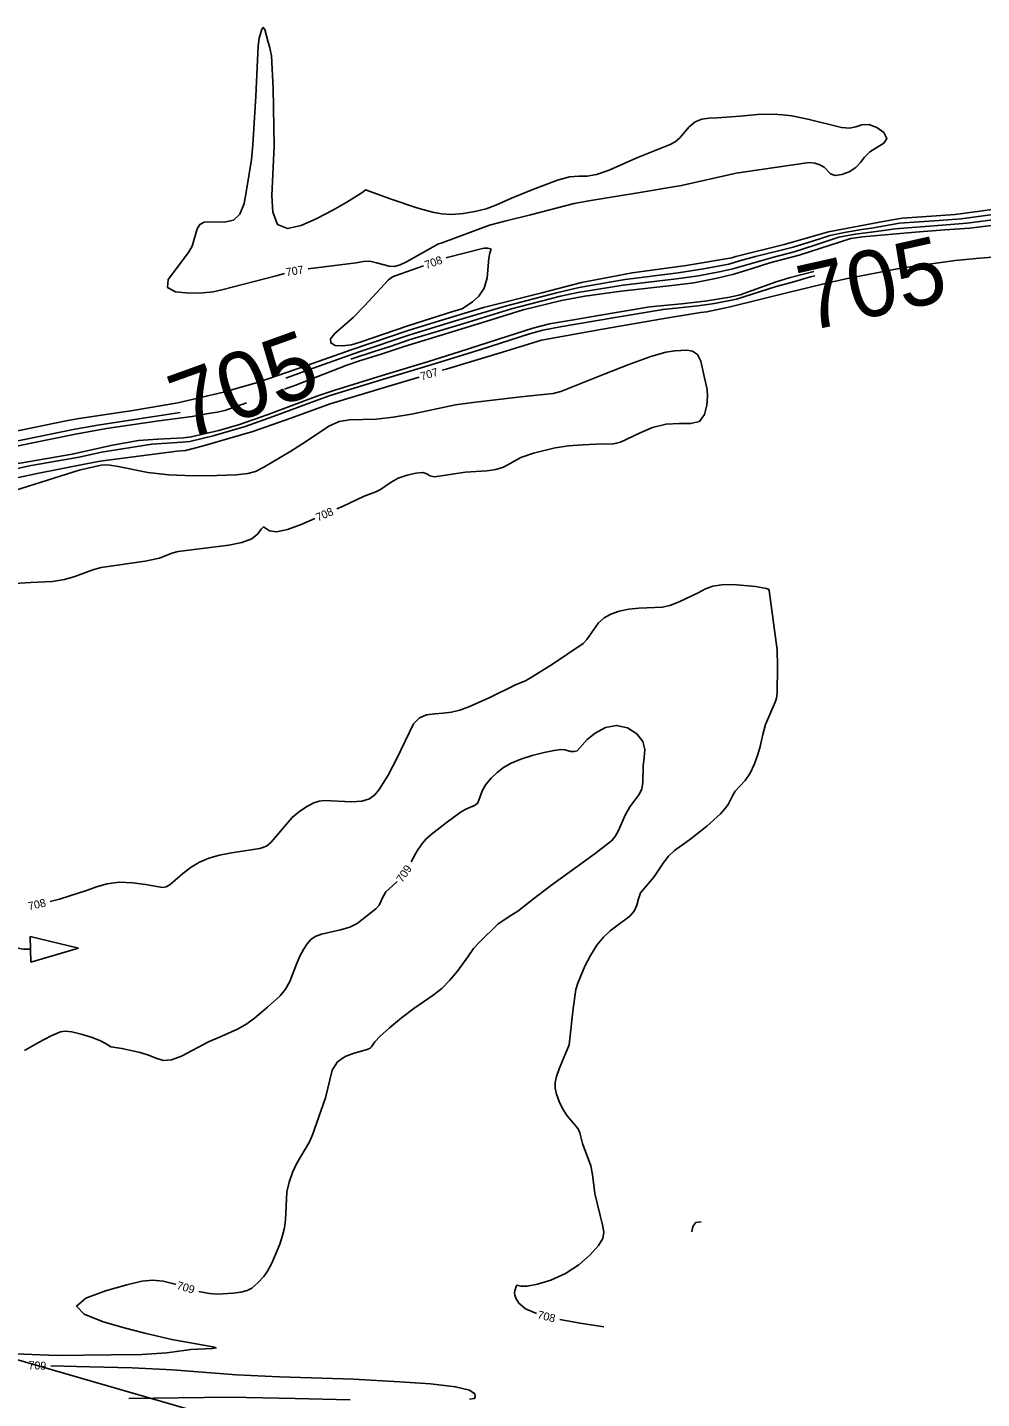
# Model space of a CAD drawing. Extents: x -468548933 to 3387700, y -306089263 to 1207014.
# Drawn here: x 1840930 to 1841407, y 538847 to 539532 of the extents above; entities that cross this region are included whole.
import ezdxf

# ---------------------------------------------------------------- set-up
doc = ezdxf.new("R2010")
doc.units = 0
for name, color, linetype in [('DT_X_Contour_Minor', 7, 'Continuous'), ('Level 19', 7, 'Continuous'), ('Level 56', 7, 'Continuous'), ('SC_Scratch1', 7, 'Continuous')]:
    doc.layers.add(name, color=color, linetype=linetype)

msp = doc.modelspace()

# ---------------------------------------------------------------- linework, layer by layer
at = {"layer": 'DT_X_Contour_Minor'}
for points in [[(1841070.63, 539411.28), (1841094.59, 539414.28), (1841098.25, 539414.92), (1841101.45, 539414.99), (1841104.77, 539414.29), (1841111.21, 539412.47), (1841113.9, 539412.4), (1841116.59, 539413.16), (1841119.79, 539414.74), (1841135.82, 539423.66), (1841137.2, 539424.03), (1841161.32, 539432.95), (1841168.97, 539435.07), (1841181.73, 539438.24), (1841203.72, 539443.89), (1841212.05, 539445.37), (1841233.42, 539448.92), (1841257.34, 539452.83), (1841284.64, 539458.97), (1841295.98, 539460.75), (1841321.05, 539464.34), (1841323.89, 539464.03), (1841326.45, 539463.23), (1841328.57, 539461.94), (1841331.85, 539458.75), (1841334.13, 539457.93), (1841337.4, 539458.28), (1841341.1, 539459.65), (1841344.4, 539461.78), (1841346.78, 539464.36), (1841348.83, 539467.1), (1841351.45, 539469.68), (1841358.49, 539474.03), (1841360.01, 539476.43), (1841358.51, 539479.28), (1841354.96, 539481.9), (1841350.92, 539483.4), (1841347.52, 539483.26), (1841344.51, 539482.26), (1841341.23, 539481.53), (1841337.26, 539481.89), (1841320.54, 539486.09), (1841312.39, 539487.62), (1841307.76, 539488.23), (1841303.22, 539488.51), (1841295.34, 539488.35), (1841286.64, 539487.58), (1841275.18, 539486.64), (1841271.21, 539486.46), (1841267.49, 539485.96), (1841264.12, 539484.63), (1841261.19, 539482.21), (1841256.3, 539476.55), (1841254.08, 539474.68), (1841251.69, 539473.41), (1841234.98, 539466.7), (1841221.14, 539460.48), (1841214.89, 539458.3), (1841210.12, 539457.59), (1841206.01, 539457.56), (1841201.36, 539457.13), (1841195.38, 539455.51), (1841183.01, 539450.85), (1841172.29, 539446.5), (1841164.52, 539443.02), (1841159.62, 539441.26), (1841154.06, 539439.8), (1841148.2, 539438.81), (1841142.51, 539438.44), (1841137.36, 539438.75), (1841132.77, 539439.56), (1841125.06, 539441.68), (1841112.58, 539445.92), (1841099.35, 539450.63), (1841098.06, 539449.58), (1841089.99, 539444.5), (1841082.96, 539440.46), (1841075.05, 539436.29), (1841067.19, 539432.83), (1841060.32, 539431.37), (1841055.4, 539433.35), (1841053.05, 539439.52), (1841052.57, 539447.87), (1841053.69, 539472.46), (1841053.12, 539501.29), (1841052.28, 539517.74), (1841051.32, 539522.29), (1841050.65, 539524.47), (1841049, 539530.83), (1841048.23, 539531.86), (1841047.46, 539530.94), (1841046.21, 539526.41), (1841045.7, 539522.58), (1841044.44, 539497.49), (1841043.02, 539473.13), (1841042.29, 539465.8), (1841039.91, 539450.48), (1841038.61, 539443.89), (1841036.49, 539438.5), (1841033.34, 539435.59), (1841029.51, 539434.64)], [(1840922.25, 539329.55), (1840949.7, 539335.19), (1840956.21, 539336.43), (1840982.93, 539340.45), (1841005.45, 539344.29), (1841028.32, 539349.57), (1841045.28, 539354.45), (1841070.02, 539362.87), (1841092.19, 539370.66), (1841120.71, 539380.38), (1841134.15, 539384.58), (1841158.38, 539391.84), (1841187.45, 539399.27), (1841207.27, 539404.37), (1841222.08, 539407.29), (1841232.58, 539409.22), (1841259.65, 539412.88), (1841282.39, 539416.79), (1841284.5, 539417.39), (1841308.65, 539423.35), (1841330.83, 539429.71), (1841358.98, 539435.09), (1841367.65, 539436.57), (1841377.39, 539437.22), (1841394.09, 539438.31), (1841418.72, 539441.67)], [(1841059.52, 539356.57), (1841070.84, 539360.65), (1841096.15, 539369.74), (1841120.94, 539378.02), (1841143.08, 539384.81), (1841168.58, 539392.39), (1841195.49, 539399.31), (1841206.06, 539401.8), (1841221.25, 539404.58), (1841229.13, 539405.91), (1841255.6, 539409.26), (1841268.3, 539411.22), (1841280.91, 539413.54), (1841286.37, 539415.17), (1841294.31, 539417.31), (1841313.14, 539422.12), (1841326.48, 539426.26), (1841331.48, 539427.89), (1841339.65, 539429.6), (1841348.48, 539431.05), (1841352.33, 539431.59), (1841366.24, 539433.95), (1841385.91, 539435.31), (1841397.12, 539436.18), (1841419.05, 539439.13)], [(1841029.51, 539434.64), (1841018.73, 539434.46), (1841016.47, 539433.37), (1841015.16, 539431.26), (1841012.69, 539422.55), (1841010.86, 539419.45), (1841000.66, 539405.86), (1841000.36, 539401.89), (1841004.41, 539399.71), (1841011.11, 539399.01), (1841017.95, 539399.2), (1841023.12, 539399.79), (1841027.5, 539400.75), (1841054.63, 539407.79), (1841058.87, 539408.88)], [(1841058.9, 539351.07), (1841064, 539352.91), (1841090.01, 539363.03), (1841096.34, 539365.27), (1841107.19, 539368.57), (1841114.11, 539370.85), (1841118.64, 539372.46), (1841142.61, 539379.65), (1841162.58, 539385.88), (1841178.23, 539390.77), (1841197.33, 539395.39), (1841208.95, 539397.55), (1841227.12, 539400.02), (1841253.93, 539403.03), (1841263.4, 539404.27), (1841275.11, 539406.52), (1841283.45, 539408.47), (1841292.56, 539411.37), (1841301.5, 539414.17), (1841316.16, 539417.98), (1841342.04, 539426.35), (1841347.87, 539427.18), (1841374.14, 539429.59), (1841389.03, 539430.67), (1841401.38, 539431.56), (1841423.01, 539434.15)], [(1841091.98, 539366.04), (1841092.47, 539366.22), (1841104.1, 539369.99), (1841111.73, 539372.42), (1841121.17, 539375.67), (1841146.31, 539383.29), (1841172.27, 539391.26), (1841196.76, 539397.5), (1841205.55, 539399.35), (1841228.12, 539402.97), (1841254.77, 539406.14), (1841265.85, 539407.74), (1841277.01, 539409.81), (1841282.97, 539411.2), (1841302.73, 539416.91), (1841313.69, 539419.76), (1841323.41, 539422.82), (1841336.04, 539426.97), (1841344.18, 539428.59), (1841349.43, 539429.23), (1841355.91, 539430.06), (1841364.1, 539431.26), (1841389.83, 539433.14), (1841399.96, 539433.98), (1841418.18, 539436.35)], [(1841139.64, 539416.71), (1841140.18, 539416.9), (1841157.78, 539421.29), (1841158.7, 539421.54), (1841160.45, 539421.59), (1841162.04, 539421.17), (1841162, 539420.59), (1841161.56, 539419.22), (1841161.06, 539416.48), (1841160.08, 539406.76), (1841158.61, 539401.63), (1841155.99, 539397.57), (1841152.87, 539394.64), (1841147.62, 539391.23), (1841143.56, 539389.98), (1841120.49, 539382.73), (1841096.65, 539374.48), (1841092.28, 539373.31), (1841087.86, 539372.65), (1841084.21, 539372.94), (1841081.98, 539374.16), (1841081.75, 539376.15), (1841083.93, 539378.82), (1841093.17, 539386.96), (1841098.75, 539392.64), (1841110.81, 539405.79), (1841112.77, 539407.22), (1841116.99, 539408.64), (1841128.34, 539412.68)], [(1841606.23, 539410.28), (1841597.87, 539410.78), (1841574.79, 539413.83), (1841547.23, 539414.25), (1841517.84, 539415.74), (1841489.57, 539416.96), (1841476.12, 539417.79), (1841458.36, 539418.68), (1841431.77, 539418.62), (1841406.52, 539416.54), (1841394.13, 539415.34), (1841366.92, 539411.49), (1841340.24, 539406.31), (1841331.22, 539404.34), (1841311.34, 539399.52), (1841281.61, 539392.22), (1841270.02, 539389.78), (1841266.76, 539389.37), (1841247.56, 539386.16), (1841217.82, 539381.06), (1841187.38, 539375.6), (1841167.74, 539369.54), (1841139.63, 539361.08), (1841137.67, 539360.5)], [(1841323.91, 539407.68), (1841321.8, 539407.15), (1841312.73, 539404.6), (1841304.62, 539402.37), (1841284.73, 539396.12), (1841273.85, 539393.96), (1841265.44, 539392.78), (1841248.06, 539390.93), (1841224.07, 539386.91), (1841196.67, 539382.19), (1841187.91, 539380.53), (1841181.36, 539378.66), (1841157.02, 539370.91), (1841132.15, 539363.17), (1841108.33, 539356.06), (1841081.64, 539347.83), (1841075.64, 539345.7), (1841053.1, 539337.39), (1841039.11, 539332.41), (1841023.18, 539327.83), (1841011.58, 539324.98), (1841007.66, 539324.53), (1840992.43, 539323.64), (1840967.38, 539319.55), (1840956.25, 539317.16), (1840932.21, 539312.9), (1840917.05, 539309.66)], [(1841323.4, 539409.88), (1841311.17, 539406.68), (1841304.67, 539404.63), (1841286.62, 539398.25), (1841281.4, 539396.99), (1841269, 539395.01), (1841257.26, 539393.71), (1841241.55, 539392.25), (1841214.84, 539387.67), (1841203.37, 539385.65), (1841191.3, 539383.64), (1841183.01, 539381.61), (1841169.93, 539377.41), (1841146.68, 539369.9), (1841130.27, 539364.75), (1841109.78, 539358.64), (1841084.01, 539350.6), (1841075.52, 539347.79), (1841050.2, 539338.31), (1841036.28, 539333.42), (1841025.93, 539330.48), (1841012.24, 539327.22), (1841008.44, 539326.72), (1840995.49, 539326.06), (1840985.77, 539325.37), (1840972.79, 539323.06), (1840952.69, 539318.55), (1840925.74, 539313.91)], [(1840924.54, 539300.52), (1840956.23, 539310.59), (1840967.16, 539313.03), (1840969.22, 539313.22), (1840971.57, 539313.07), (1840975.66, 539312.4), (1840990.44, 539309.43), (1841000.98, 539308.19), (1841013.1, 539307.72), (1841025.03, 539307.88), (1841034.63, 539308.33), (1841040.54, 539308.89), (1841044.37, 539309.97), (1841048.48, 539312.11), (1841062.03, 539320.11), (1841069.39, 539324.82), (1841081.04, 539332.62), (1841086.11, 539334.88), (1841091.39, 539335.71), (1841104.58, 539336), (1841113.17, 539337.01), (1841122.24, 539338.6), (1841144.34, 539343.18), (1841153.01, 539344.49), (1841176.92, 539347.18), (1841193.11, 539348.97), (1841196.99, 539349.84), (1841218.67, 539358.51), (1841231.01, 539363.35), (1841242.02, 539367.37), (1841249.41, 539369.53), (1841253.91, 539370.29), (1841260.03, 539370.55), (1841262.86, 539370.14), (1841265.22, 539368.45), (1841266.89, 539365.05), (1841268.86, 539356.7), (1841270.09, 539350.92), (1841270.3, 539347.59), (1841270.04, 539343.06), (1841268.85, 539338.38), (1841266.23, 539334.99), (1841261.88, 539333.83), (1841256.15, 539333.88), (1841249.61, 539333.59), (1841242.85, 539331.84), (1841236.61, 539329.24), (1841226.84, 539324.65), (1841224.89, 539324.07), (1841223.18, 539323.82), (1841214.62, 539323.54), (1841207.92, 539323.33), (1841200.79, 539322.78), (1841194.07, 539321.75), (1841183.35, 539319.15), (1841177.01, 539316.97), (1841171.64, 539313.93), (1841168.35, 539312.17), (1841164.5, 539310.85), (1841160.02, 539310.27), (1841149.35, 539309.67), (1841133.85, 539307.31), (1841131.53, 539307.79), (1841130.04, 539308.71), (1841128.03, 539309.34), (1841124.52, 539309.12), (1841120.09, 539308.11), (1841115.73, 539306.52), (1841112.17, 539304.58), (1841106.87, 539300.92), (1841104.56, 539299.75), (1841098.68, 539297.54), (1841088.12, 539292.55), (1841085.03, 539291.21)], [(1841126.16, 539357.12), (1841110.92, 539352.65), (1841081.72, 539343.75), (1841061.95, 539336.58), (1841043.03, 539329.88), (1841017.68, 539322.52), (1841009.34, 539320.38), (1841005.11, 539320.08), (1840990.98, 539318.29), (1840966.66, 539315.07), (1840958.8, 539313.56), (1840935.15, 539308.87), (1840910.25, 539303.6)], [(1840915.97, 539320.82), (1840932.2, 539324.07), (1840954.34, 539328.62), (1840969.76, 539331.34), (1840996.08, 539335.21), (1841008.86, 539336.84), (1841012.73, 539337.37), (1841019.88, 539338.67), (1841025.19, 539339.53), (1841028.97, 539340.46), (1841039.8, 539344.2)], [(1840618.54, 539263.67), (1840637.79, 539268.09), (1840664.56, 539273.66), (1840689.84, 539278.54), (1840703.88, 539280.87), (1840714.02, 539282.17), (1840724.81, 539283.75), (1840733.92, 539285.29), (1840755, 539287.72), (1840768.87, 539289.34), (1840797.81, 539293.75), (1840808.53, 539295.67), (1840814.5, 539297.11), (1840831.62, 539302.36), (1840855.06, 539308.38), (1840873.5, 539313.18), (1840898.33, 539319.49), (1840919.77, 539324.07), (1840928.88, 539325.89), (1840954.02, 539331.06), (1840966.44, 539333.22), (1840993.7, 539337.34), (1841006.71, 539339.49)], [(1841074.03, 539286.41), (1841067.18, 539283.42), (1841060.34, 539280.89), (1841054.89, 539279.74), (1841051.41, 539280.34), (1841048.29, 539282.23), (1841047.24, 539281.06), (1841045.55, 539278.74), (1841042.45, 539276.26), (1841037.45, 539274.4), (1841031.03, 539273.15), (1841005.64, 539269.99), (1841002.55, 539269.15), (1840996.3, 539266.6), (1840989.22, 539265.16), (1840967.17, 539261.94), (1840963.06, 539260.79), (1840954.07, 539257.4), (1840948.78, 539255.9), (1840942.85, 539254.99), (1840932.06, 539254.39), (1840923.77, 539253.93)], [(1840941.65, 539095.08), (1840946.28, 539096.15), (1840960.28, 539100.68), (1840964.82, 539102.3), (1840970.12, 539103.8), (1840976.22, 539104.63), (1840982.94, 539104.42), (1840989.42, 539103.55), (1840997.77, 539102.07), (1840999.74, 539102.3), (1841001.68, 539103.56), (1841008.08, 539109.03), (1841012.13, 539112.11), (1841016.4, 539114.67), (1841021.05, 539116.67), (1841026.32, 539118.2), (1841032.27, 539119.34), (1841046.46, 539121.49), (1841049.77, 539122.72), (1841050.87, 539123.5), (1841052.11, 539124.72), (1841062.63, 539137.07), (1841066.48, 539140.17), (1841070.27, 539142.61), (1841073.55, 539144.29), (1841076.1, 539145.21), (1841078.61, 539145.5), (1841092.46, 539144.81), (1841097.55, 539145.14), (1841101.28, 539146.29), (1841103.96, 539148.26), (1841106.17, 539150.97), (1841110.61, 539158.11), (1841114.92, 539166.41), (1841123.36, 539183.76), (1841126.24, 539186.74), (1841129.85, 539188.27), (1841133.94, 539188.82), (1841138.16, 539189.08), (1841142.27, 539189.62), (1841146.45, 539190.64), (1841150.99, 539192.24), (1841161.19, 539196.88), (1841174.63, 539203.46), (1841179.23, 539205.38), (1841182.69, 539207.26), (1841192.75, 539213.64), (1841208.13, 539223.93), (1841209.99, 539225.99), (1841215.85, 539234.32), (1841218.62, 539236.71), (1841222.04, 539238.63), (1841226.2, 539240.07), (1841231.03, 539241.04), (1841236.05, 539241.61), (1841247.81, 539242.15), (1841251.55, 539243), (1841256.11, 539244.73), (1841265.58, 539249.3), (1841269.38, 539251.21), (1841273.05, 539252.57), (1841277.46, 539253.3), (1841283.16, 539253.38), (1841294.27, 539252.5), (1841299.81, 539251.46), (1841301.01, 539251.03), (1841301.21, 539250.4), (1841301.45, 539248.03), (1841305.2, 539220.82), (1841305.37, 539212.46), (1841305.12, 539199.12), (1841304.76, 539196.72), (1841304.07, 539194.56), (1841299.3, 539183.45), (1841297.93, 539178.55), (1841296.65, 539172.51), (1841295.52, 539168.52), (1841293.86, 539163.78), (1841291.67, 539159.22), (1841289.05, 539155.55), (1841284.19, 539150.19), (1841282.74, 539147.91), (1841280.59, 539143.53), (1841278.99, 539141.3), (1841276.72, 539138.87), (1841269.89, 539132.71), (1841261.34, 539125.92), (1841253.84, 539120.49), (1841250.78, 539117.61), (1841248.19, 539114.19), (1841243.51, 539107.17), (1841236.86, 539099.27), (1841235.81, 539096.32), (1841234.99, 539093.2), (1841233.71, 539090.22), (1841231.45, 539087.61), (1841225.05, 539082.87), (1841221.64, 539080.29), (1841218.29, 539077.16), (1841215.01, 539073.13), (1841211.86, 539068.05)], [(1841016.01, 538900.14), (1841016.63, 538899.96), (1841021.41, 538899.04), (1841025.38, 538898.81), (1841033.1, 538899.29), (1841036.96, 538899.8), (1841040.22, 538900.61), (1841042.51, 538901.77), (1841045.45, 538904.52), (1841048.53, 538907.57), (1841050.39, 538910.26), (1841052.46, 538914.27), (1841056.43, 538923.84), (1841057.89, 538928.05), (1841058.87, 538931.92), (1841059.38, 538935.9), (1841059.97, 538949.95), (1841061.08, 538954.83), (1841062.78, 538959.52), (1841064.86, 538963.9), (1841071.26, 538974.96), (1841072.78, 538978.38), (1841079.31, 538996.96), (1841082.64, 539010.81), (1841085.26, 539014.83), (1841089.21, 539017.58), (1841093.68, 539019.25), (1841100.2, 539021.05), (1841101.63, 539021.73), (1841102.35, 539022.42), (1841104, 539024.87), (1841106.65, 539027.64), (1841111.37, 539031.9), (1841117.34, 539036.89), (1841123.41, 539041.56), (1841133.23, 539048.26), (1841137.44, 539051.59), (1841141.56, 539055.72), (1841145.33, 539060.2), (1841150.55, 539067.43), (1841153.24, 539071.45), (1841156.04, 539074.29), (1841165.63, 539083.78), (1841171.95, 539087.96), (1841175.49, 539090.25), (1841183.37, 539096.34), (1841191.74, 539102.85), (1841214.06, 539118.96), (1841222.35, 539125.41), (1841224.21, 539127.53), (1841225.58, 539130.13), (1841229.14, 539138.22), (1841231.39, 539142.31), (1841236, 539148.28), (1841237.5, 539151.17), (1841238.01, 539154.69), (1841238.1, 539162.87), (1841238.69, 539166.99), (1841239.01, 539171.02), (1841238.02, 539175.03), (1841234.98, 539178.89), (1841230.34, 539181.87), (1841224.86, 539183.06), (1841219.27, 539181.9), (1841214.19, 539179.19), (1841210.22, 539176.04), (1841205.15, 539170.35), (1841203.69, 539169.94), (1841202.04, 539170.04), (1841198.9, 539170.79), (1841196.9, 539170.93), (1841193.63, 539170.56), (1841188.62, 539169.53), (1841182.69, 539167.98), (1841176.92, 539166.13), (1841172.18, 539164.16), (1841168.36, 539162), (1841165.08, 539159.5), (1841162.09, 539156.61), (1841159.56, 539153.55), (1841157.75, 539150.59), (1841155.5, 539144.26), (1841154.09, 539143.23), (1841149.49, 539141.24), (1841146.58, 539139.47), (1841139.71, 539134.36), (1841132.19, 539128.52), (1841129.41, 539126.14), (1841127.29, 539123.48), (1841126.49, 539122.2), (1841125.66, 539121.16), (1841124.41, 539119.15), (1841122.08, 539114.77)], [(1841115.08, 539105.01), (1841114.81, 539104.73), (1841109.51, 539099.86), (1841108.11, 539097.53), (1841106.2, 539093.19), (1841104.56, 539091.41), (1841095.08, 539084.04), (1841091.5, 539082.24), (1841086.83, 539080.86), (1841077.32, 539078.72), (1841074.15, 539077.52), (1841071.96, 539075.98), (1841070.18, 539073.89), (1841068.35, 539071.11), (1841066.5, 539067.7), (1841064.75, 539063.76), (1841061.49, 539055.12), (1841059.41, 539051.15), (1841056.69, 539047.84), (1841050.31, 539042.28), (1841043.87, 539036.68), (1841040.07, 539033.94), (1841035.61, 539031.4), (1841027.53, 539027.64), (1841020.75, 539024.85), (1841007.41, 539017.76), (1841002.3, 539015.85), (1840998.38, 539015.59), (1840995.06, 539016.57), (1840991.38, 539018.1), (1840986.73, 539019.58), (1840977.52, 539021.6), (1840971.94, 539022.44), (1840969.37, 539024.11), (1840966.57, 539025.5), (1840962.19, 539027.15), (1840957.1, 539028.74), (1840952.48, 539029.86), (1840949.2, 539030.21), (1840946.85, 539029.87), (1840942.16, 539027.86), (1840935.92, 539024.58), (1840928.88, 539020.58)], [(1841211.86, 539068.05), (1841209.05, 539062.66), (1841205.4, 539054.29), (1841204.51, 539051.07), (1841203.19, 539041.49), (1841201.16, 539023.44), (1841196.16, 539011.44), (1841194.85, 539007.61), (1841194.16, 539004.5), (1841194.16, 539001.75), (1841194.84, 538998.76), (1841196.18, 538995.14), (1841198.01, 538991.31), (1841200.11, 538987.88), (1841205.7, 538981.46), (1841206.52, 538979.42), (1841207.83, 538974.15), (1841211.98, 538962.85), (1841212.75, 538958.6), (1841213.97, 538949.05), (1841216.58, 538938.11), (1841217.81, 538933.37), (1841218.42, 538929.74), (1841217.92, 538926.6), (1841215.79, 538923.05), (1841211.69, 538918.49), (1841205.99, 538913.52), (1841199.23, 538909.04), (1841192.03, 538905.77), (1841185.32, 538903.74), (1841180.08, 538902.82), (1841177.01, 538902.79), (1841175.02, 538903.2), (1841174.6, 538902.62), (1841173.93, 538900.42), (1841173.77, 538899.44), (1841173.91, 538898.33), (1841174.55, 538896.72), (1841176.04, 538894.33), (1841179.38, 538891.49), (1841184.8, 538889.05)], [(1841262.41, 538929.9), (1841262.89, 538932.53), (1841264.42, 538934.65), (1841267.08, 538934.95)], [(1840919.79, 538869.2), (1840945.25, 538868.07), (1840958.27, 538868.3), (1840972.01, 538868.54), (1840987.44, 538868.67), (1840999.92, 538869.47), (1841009.75, 538870.75), (1841011.92, 538871.17), (1841022.79, 538871.55), (1841024.61, 538871.93), (1841022.95, 538872.52), (1841002.42, 538876.1), (1840989.06, 538879.27), (1840979.41, 538881.79), (1840968.17, 538885.02), (1840958.66, 538888.79), (1840954.92, 538892.83), (1840959.55, 538896.86), (1840969.41, 538900.52), (1840979.93, 538903.41), (1840987.58, 538905.2), (1840993.08, 538905.82), (1840998.18, 538905.28), (1841004.21, 538903.71), (1841004.52, 538903.62)], [(1841196.41, 538886.04), (1841206.62, 538884.25), (1841218.43, 538882.39)], [(1840942.09, 538862.94), (1840961.34, 538862.49), (1840982.62, 538861.96), (1841002.85, 538861), (1841034.77, 538858.47), (1841056.3, 538857.46), (1841093.34, 538856.28), (1841116.54, 538855.04), (1841131.76, 538853.93), (1841144.37, 538852.47), (1841151.36, 538850.72), (1841153.9, 538848.95), (1841154.23, 538847.51), (1841153.84, 538846.65), (1841151.24, 538846.24)], [(1841091.69, 538845.98), (1841064.13, 538846.61), (1841031.74, 538847.26), (1841005.67, 538846.97), (1840980.96, 538846.58)]]:
    msp.add_lwpolyline(points, dxfattribs=at)
at = {"layer": 'Level 56'}
for p, q in [((1840931.68, 539077.57), (1840955.81, 539071.65)), ((1840931.96, 539064.69), (1840931.68, 539077.57)), ((1840955.81, 539071.65), (1840931.96, 539064.69))]:
    msp.add_line(p, q, dxfattribs=at)
msp.add_spline([(1840931.84, 539071.19), (1840930.89, 539071.17), (1840920.97, 539073.2), (1840914.67, 539075.24), (1840902.19, 539063.94), (1840887.38, 539075.99), (1840870.85, 539063.25), (1840867.31, 539069.87), (1840850.84, 539069.34)], degree=3, dxfattribs=at)
at = {"layer": 'SC_Scratch1'}
msp.add_lwpolyline([(1834448.38, 536360.46), (1835055.83, 534489.39), (1836664.2, 534206.16), (1839225.76, 534394.17), (1842361.7, 536308.3), (1842189.37, 536805.14), (1841581.79, 538676.58), (1840313.7, 539042.49), (1837357.67, 538260.17), (1834781.04, 538194.31), (1834403.13, 536496.43)], close=True, dxfattribs=at)

# ---------------------------------------------------------------- texts
at = {"layer": 'Level 19'}
for s, height, rotation, p in [('705', 33, 12.65664, (1841320.03, 539379.85)), ('707', 4, 9.59704, (1841059.85, 539407.49)), ('708', 4, 19.60662, (1841129.72, 539411.05)), ('705', 33, 19.78996, (1841009.09, 539325.47)), ('707', 4, 16.35794, (1841127.43, 539355.41)), ('708', 4, 23.57721, (1841075.52, 539284.88)), ('709', 4, 55.76025, (1841117.7, 539104.13)), ('708', 4, 12.96031, (1840931.14, 539090.6)), ('709', 4, 343.1788, (1841004.65, 538901.49)), ('708', 4, 345.93473, (1841185, 538886.76)), ('709', 4, 357.68036, (1840930.75, 538861.33))]:
    msp.add_text(s, height=height, rotation=rotation, dxfattribs=at).set_placement(p)

doc.saveas('drawing.dxf')
